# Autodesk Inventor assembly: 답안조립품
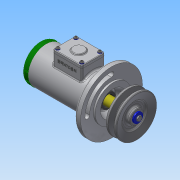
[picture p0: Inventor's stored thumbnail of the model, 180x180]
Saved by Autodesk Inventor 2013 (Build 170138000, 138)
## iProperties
Created: 2017-05
Part Number: 답안조립품
Document SubType Name: Assembly
Designer: Administrator
Author: Administrator
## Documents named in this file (20)
- C:\Users\Administrator\Desktop\470508V1022\답안조립품.iam
- C:\Users\Administrator\Desktop\470508V1022\본체.ipt
- C:\Users\Administrator\Desktop\470508V1022\V-벨트풀리.ipt
- C:\Users\Administrator\Desktop\470508V1022\너트 M10.ipt
- C:\Users\Administrator\Desktop\470508V1022\멈춤링 15 x 1.ipt
- C:\Users\Administrator\Desktop\470508V1022\멈춤링 35x1.6.ipt
- C:\Users\Administrator\Desktop\470508V1022\베어링 15 x 35 x 11.ipt
- C:\Users\Administrator\Desktop\470508V1022\볼트 M4 x 10.ipt
- C:\Users\Administrator\Desktop\470508V1022\부시1.ipt
- C:\Users\Administrator\Desktop\470508V1022\부시2.ipt
- C:\Users\Administrator\Desktop\470508V1022\사이드 커버.ipt
- 사이드 커버.ipt
- C:\Users\Administrator\Desktop\470508V1022\십자볼트 M3 x 10.ipt
- C:\Users\Administrator\Desktop\470508V1022\오일 실 15 25 7.ipt
- C:\Users\Administrator\Desktop\470508V1022\와셔 3x6.ipt
- C:\Users\Administrator\Desktop\470508V1022\와셔 4x16.ipt
- C:\Users\Administrator\Desktop\470508V1022\와셔 10x21.ipt
- C:\Users\Administrator\Desktop\470508V1022\축.ipt
- C:\Users\Administrator\Desktop\470508V1022\키 4 x 4 x 18.ipt
- C:\Users\Administrator\Desktop\470508V1022\탑 커버.ipt
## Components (2 placed, 2 different names)
1. V-벨트풀리:1
2. ISO 4017 M4 x 10:1
